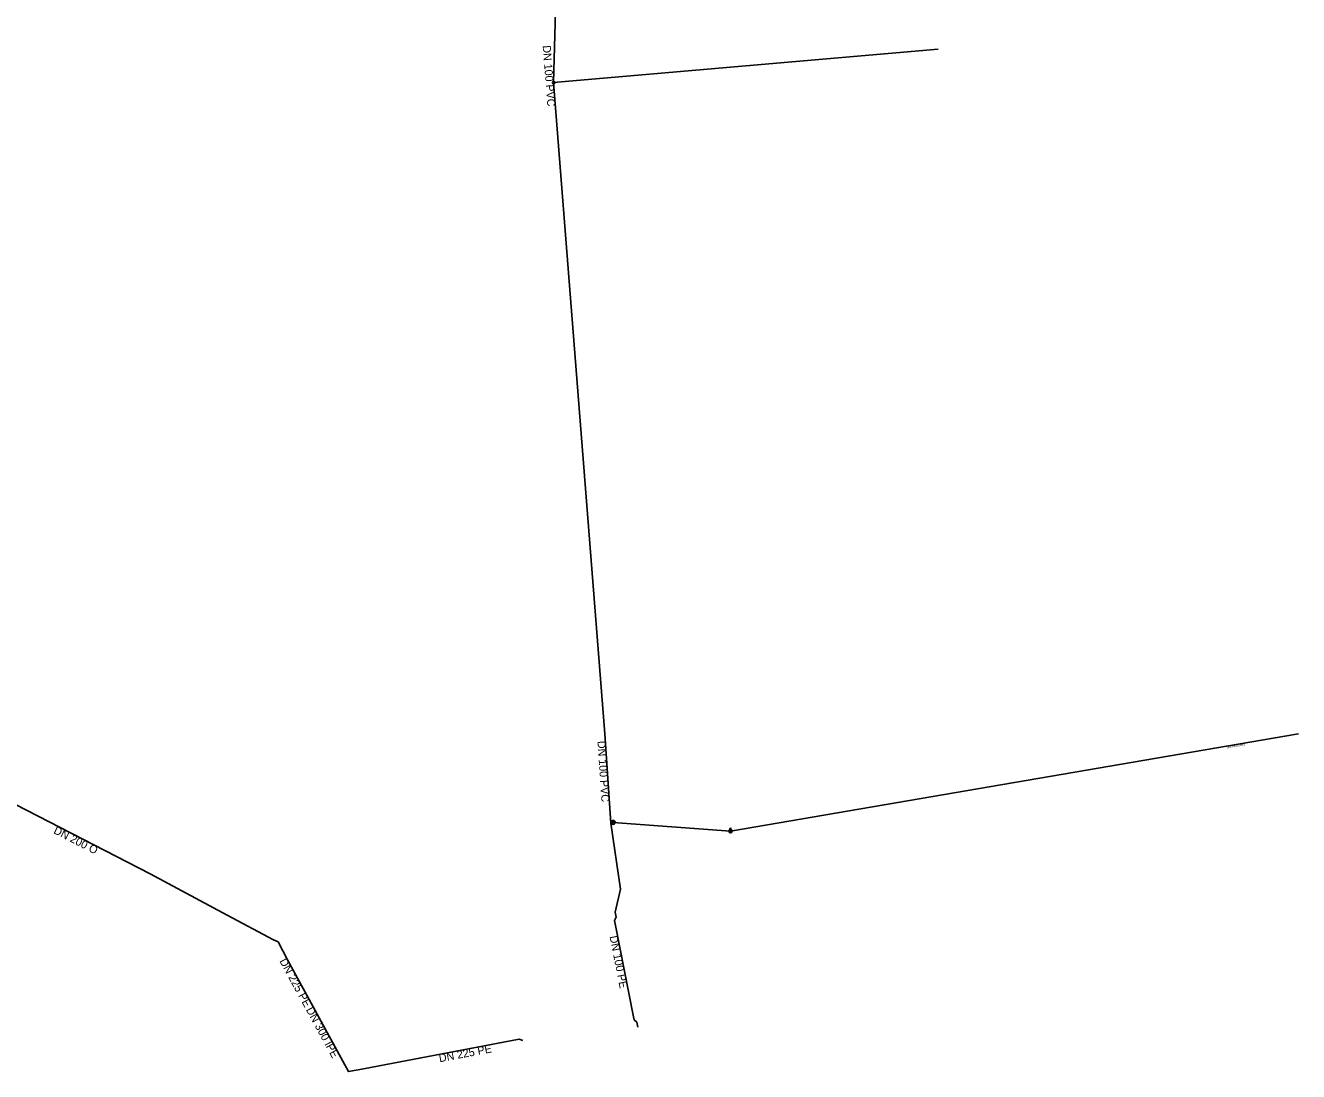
# Model space of a CAD drawing. Extents: x -491015 to -489994, y -1125687 to -1125176.
# Drawn here: x -490249.3 to -489994, y -1125586.2 to -1125376.4 of the extents above; entities that cross this region are included whole.
import ezdxf

# ---------------------------------------------------------------- set-up
doc = ezdxf.new("R2010")
doc.units = 0
for name, color, linetype in [('_kalosvod_', 7, 'Continuous'), ('_pripojka_priblizne_', 7, 'Continuous'), ('_voda_smvak_prevzato_z_dokumentace_', 7, 'Continuous'), ('_voda_smvak_priblizne_', 7, 'Continuous'), ('_vodovodni_chranicka_', 7, 'Continuous'), ('Default', 7, 'Continuous'), ('MoLevel 2', 7, 'Continuous'), ('MoLevel 27', 7, 'Continuous'), ('MoLevel 30', 7, 'Continuous'), ('MoLevel 32', 7, 'Continuous'), ('MoLevel 42', 7, 'Continuous'), ('MoLevel 46', 7, 'Continuous'), ('MoLevel 53', 7, 'Continuous'), ('MoLevel 60', 7, 'Continuous')]:
    doc.layers.add(name, color=color, linetype=linetype)

# ---------------------------------------------------------------- blocks, each defined once
blk = doc.blocks.new('_uzaver_')
at = {"layer": 'Default'}
for p, q in [((-0.035, -0.035), (0.035, 0.035)), ((0.035, -0.035), (-0.035, 0.035))]:
    blk.add_line(p, q, dxfattribs=at)
for radius in [0.05, 0.0025]:
    blk.add_circle((0, 0), radius, dxfattribs=at)
blk = doc.blocks.new('_uzaver_pripojka_')
at = {"layer": 'Default'}
for p, q in [((-0.035, -0.035), (0.035, 0.035)), ((0.035, -0.035), (-0.035, 0.035))]:
    blk.add_line(p, q, dxfattribs=at)
for radius in [0.05, 0.0025]:
    blk.add_circle((0, 0), radius, dxfattribs=at)
blk = doc.blocks.new('_sachta_voda_')
at = {"layer": 'Default'}
blk.add_lwpolyline([(-0.01, 0.065), (0, 0.035), (0.01, 0.065)], dxfattribs=at)
blk.add_circle((0, 0), 0.035, dxfattribs=at)
blk = doc.blocks.new('_poklop_voda_')
at = {"layer": 'Default'}
blk.add_lwpolyline([(-0.02, 0.02), (0.02, 0.02), (0.02, -0.02), (-0.02, -0.02), (-0.02, 0.02)], dxfattribs=at)

msp = doc.modelspace()

# ---------------------------------------------------------------- linework, layer by layer
at = {"layer": '_kalosvod_'}
msp.add_line((-490143.37, -1125387.89), (-490066.27, -1125381.18), dxfattribs=at)
at = {"layer": '_pripojka_priblizne_'}
msp.add_lwpolyline([(-490131.88, -1125536.38), (-490131.42, -1125536.23), (-490107.92, -1125538.01), (-489994.02, -1125518.48)], dxfattribs=at)
at = {"layer": '_voda_smvak_prevzato_z_dokumentace_'}
for points in [[(-490199.54, -1125559.79), (-490208.83, -1125554.81), (-490224.29, -1125546.52), (-490255.87, -1125530.33), (-490269.42, -1125523.41), (-490281.75, -1125517.39)], [(-490133.08, -1125518.49), (-490131.88, -1125536.38), (-490129.95, -1125549.64), (-490131.02, -1125554.25)], [(-490126.47, -1125577.28), (-490126.66, -1125576.3), (-490127.22, -1125575.85), (-490127.35, -1125575.2), (-490131.04, -1125556.57), (-490131.17, -1125555.92), (-490130.83, -1125555.21), (-490131.02, -1125554.25)], [(-490199.54, -1125559.79), (-490198.63, -1125560.22), (-490196.7, -1125563.79), (-490185.24, -1125584.88), (-490184.53, -1125586.2), (-490182.56, -1125585.83), (-490170.29, -1125583.49), (-490150.27, -1125579.68), (-490149.55, -1125579.98)]]:
    msp.add_lwpolyline(points, dxfattribs=at)
at = {"layer": '_voda_smvak_priblizne_'}
msp.add_lwpolyline([(-490139.04, -1125176.48), (-490138.29, -1125207.22), (-490143.37, -1125387.89), (-490133.08, -1125518.49)], dxfattribs=at)
at = {"layer": '_vodovodni_chranicka_'}
for p, q in [((-490127.35, -1125575.2), (-490131.04, -1125556.57)), ((-490196.7, -1125563.79), (-490185.24, -1125584.88))]:
    msp.add_line(p, q, dxfattribs=at)

# ---------------------------------------------------------------- block references
at = {"layer": 'MoLevel 27', "xscale": 5.000000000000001, "yscale": 5.000000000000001, "rotation": 4.970070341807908}
msp.add_blockref('_uzaver_', (-490143.37, -1125387.89), dxfattribs=at)
at = {"layer": 'MoLevel 30', "xscale": 10, "yscale": 10}
msp.add_blockref('_sachta_voda_', (-490107.92, -1125538.01), dxfattribs=at)
at = {"layer": 'MoLevel 42', "xscale": 10, "yscale": 10}
msp.add_blockref('_poklop_voda_', (-490107.92, -1125538.01), dxfattribs=at)
at = {"layer": 'MoLevel 53', "xscale": 8, "yscale": 8}
msp.add_blockref('_uzaver_pripojka_', (-490131.42, -1125536.23), dxfattribs=at)

# ---------------------------------------------------------------- texts
at = {"layer": 'MoLevel 2'}
msp.add_text('DN 100 PVC', height=1.605, rotation=274.505, dxfattribs=at).set_placement((-490145.57, -1125380.47))
at = {"layer": 'MoLevel 32'}
msp.add_text('DN neznámý', height=0.455, rotation=9.7293, dxfattribs=at).set_placement((-490008.34, -1125521.4))
at = {"layer": 'MoLevel 46'}
for s, rotation, p in [('DN 100 PVC', 273.8407, (-490134.59, -1125519.94)), ('DN 200 O', 332.8573, (-490243.77, -1125538.34)), ('DN 100 PE', 281.223, (-490132.17, -1125559.12)), ('DN 225 PE', 298.5152, (-490198.39, -1125564.04)), ('DN 225 PE', 10.7647, (-490166.22, -1125584.35))]:
    msp.add_text(s, height=1.605, rotation=rotation, dxfattribs=at).set_placement(p)
at = {"layer": 'MoLevel 60'}
msp.add_text('DN 300 lPE', height=1.605, rotation=298.5152, dxfattribs=at).set_placement((-490193.08, -1125573.8))

doc.saveas('drawing.dxf')
